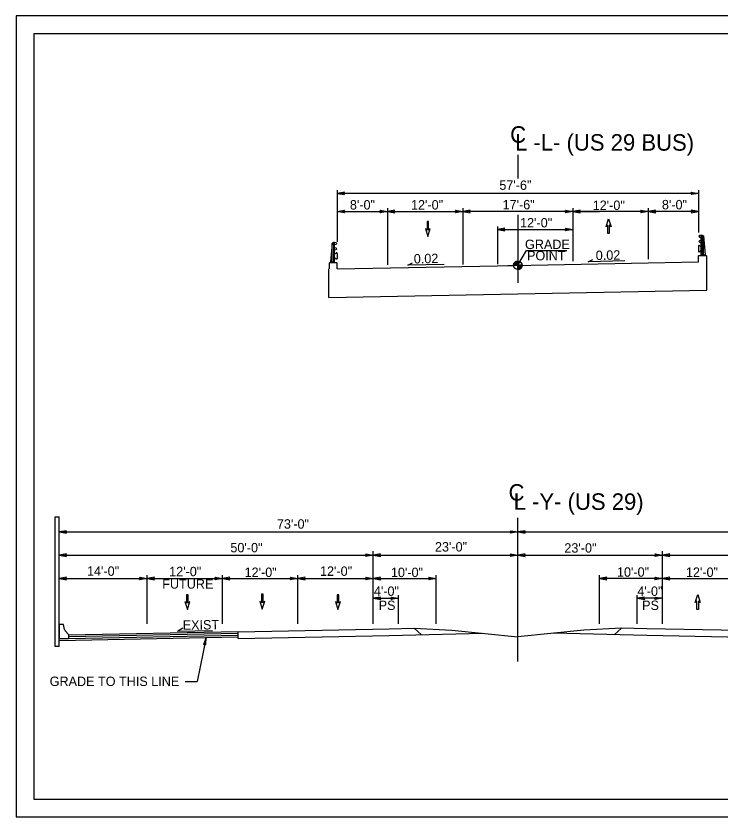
# Model space of a CAD drawing. Extents: x 1901582 to 1902252, y 193723 to 194156.
# Drawn here: x 1901677.8 to 1901790, y 193784.8 to 193912.3 of the extents above; entities that cross this region are included whole.
import ezdxf

# ---------------------------------------------------------------- set-up
doc = ezdxf.new("R2010")
doc.units = 0
for name, color, linetype in [('Old_Level_1', 7, 'Continuous'), ('Old_Level_11', 7, 'Continuous'), ('Old_Level_2', 7, 'Continuous'), ('Prop Dimension', 7, 'Continuous'), ('Prop Dimension Text', 7, 'Continuous'), ('Prop Roadway Bridge', 7, 'Continuous'), ('Scratch_Level_0', 7, 'Continuous'), ('Typical Bridge Rail CELL', 7, 'Continuous'), ('Typical Grade Point Symbol CELL', 7, 'Continuous'), ('Typical Pavement Slope CELL', 7, 'Continuous'), ('Typical Pavement Slope Information CELL', 7, 'Continuous'), ('Typical Terminator CELL', 7, 'Continuous'), ('Typical Text Centerline CELL', 7, 'Continuous'), ('Typical Text Grade Point CELL', 7, 'Continuous')]:
    doc.layers.add(name, color=color, linetype=linetype)

msp = doc.modelspace()

# ---------------------------------------------------------------- linework, layer by layer
at = {"layer": 'Old_Level_1'}
for p, q in [((1901728.9, 193884.55), (1901728.9, 193876.32)), ((1901786.4, 193884.55), (1901786.4, 193877.8)), ((1901736.9, 193881.68), (1901736.9, 193872.69)), ((1901748.9, 193881.68), (1901748.9, 193872.73)), ((1901766.4, 193881.68), (1901766.4, 193873.28)), ((1901778.4, 193881.68), (1901778.4, 193873.6)), ((1901754.4, 193878.8), (1901754.4, 193872.8)), ((1901786.41, 193875.65), (1901786.41, 193874.85)), ((1901786.82, 193875.5), (1901786.54, 193875.73)), ((1901728.48, 193874.35), (1901728.75, 193874.58)), ((1901728.89, 193874.5), (1901728.89, 193873.7)), ((1901786.4, 193874.09), (1901786.47, 193874.17)), ((1901786.4, 193873.17), (1901786.4, 193874.09)), ((1901786.47, 193874.17), (1901787.63, 193874.17)), ((1901786.82, 193875), (1901786.54, 193874.77)), ((1901786.66, 193874.16), (1901786.74, 193874.16)), ((1901787.35, 193874.16), (1901787.41, 193874.16)), ((1901787.69, 193874.1), (1901787.63, 193874.17)), ((1901787.69, 193874.1), (1901787.69, 193873.17)), ((1901727.61, 193872.95), (1901727.67, 193873.02)), ((1901727.61, 193872.95), (1901727.61, 193872.02)), ((1901728.83, 193873.02), (1901727.67, 193873.02)), ((1901727.95, 193873.01), (1901727.89, 193873.01)), ((1901728.48, 193873.85), (1901728.75, 193873.62)), ((1901728.64, 193873.01), (1901728.56, 193873.01)), ((1901728.9, 193872.94), (1901728.83, 193873.02)), ((1901728.9, 193872.02), (1901728.9, 193872.94)), ((1901754.4, 193872.53), (1901786.4, 193873.17)), ((1901787.69, 193873.17), (1901787.73, 193873.17)), ((1901787.73, 193868.67), (1901787.73, 193873.17)), ((1901727.57, 193867.47), (1901727.57, 193872.02)), ((1901728.9, 193872.02), (1901754.4, 193872.53)), ((1901727.57, 193867.47), (1901787.73, 193868.67)), ((1901713.15, 193814.26), (1901686.15, 193813.72)), ((1901713.15, 193814.26), (1901737.15, 193814.74)), ((1901713.15, 193813.18), (1901713.15, 193814.26)), ((1901737.15, 193814.74), (1901741.15, 193814.84)), ((1901737.15, 193813.67), (1901752, 193814.04)), ((1901741.15, 193814.84), (1901747.15, 193814.53)), ((1901741.15, 193814.84), (1901742.31, 193813.8)), ((1901747.15, 193814.53), (1901757.65, 193813.48)), ((1901768.15, 193814.53), (1901757.65, 193813.48)), ((1901778.15, 193813.67), (1901763.3, 193814.04)), ((1901774.15, 193814.84), (1901768.15, 193814.53)), ((1901774.15, 193814.84), (1901772.99, 193813.8)), ((1901778.15, 193814.74), (1901774.15, 193814.84)), ((1901814.15, 193814.02), (1901778.15, 193814.74)), ((1901708.06, 193813.33), (1901706.61, 193806.37)), ((1901704.7, 193806.37), (1901706.61, 193806.37))]:
    msp.add_line(p, q, dxfattribs=at)
msp.add_lwpolyline([(1901839.99, 193787.6), (1901839.99, 193909.47), (1901680.62, 193909.47), (1901680.62, 193787.6)], close=True, dxfattribs=at)
for points in [[(1901786.83, 193877.38), (1901786.98, 193877.38), (1901787.18, 193877.3), (1901787.2, 193877.3), (1901787.45, 193874.27), (1901787.45, 193874.24), (1901786.83, 193874.24), (1901786.83, 193877.38), (1901786.98, 193877.38), (1901786.98, 193874.24), (1901787.18, 193874.24), (1901787.18, 193877.3)], [(1901728.47, 193876.23), (1901728.32, 193876.23), (1901728.11, 193876.15), (1901728.09, 193876.15), (1901727.85, 193873.12), (1901727.85, 193873.09), (1901728.47, 193873.09), (1901728.47, 193876.23), (1901728.32, 193876.23), (1901728.32, 193873.09), (1901728.11, 193873.09), (1901728.11, 193876.15)], [(1901713.15, 193813.18), (1901737.15, 193813.66)], [(1901814.14, 193812.94), (1901778.15, 193813.66)]]:
    msp.add_lwpolyline(points, dxfattribs=at)
for centre, start, end in [((1901786.49, 193875.66), 50.5568, 186.0672), ((1901728.81, 193874.51), 353.9328, 129.4432), ((1901786.49, 193874.84), 173.9328, 309.4432), ((1901728.81, 193873.69), 230.5568, 6.0672)]:
    msp.add_arc(centre, 0.0824, start, end, dxfattribs=at)
for centre, major_axis, start_param, end_param in [((1901786.83, 193877.22), (-0.392, 0), 4.712389, 6.283185), ((1901786.83, 193877.22), (-0.392, 0), 0, 1.570796), ((1901786.83, 193876.39), (-0.392, 0), 4.712389, 6.283185), ((1901728.47, 193876.07), (0.392, 0), 0, 1.570796), ((1901728.47, 193876.07), (0.392, 0), 4.712389, 6.283185), ((1901728.47, 193875.24), (0.392, 0), 0, 1.570796), ((1901728.47, 193875.24), (0.392, 0), 4.712389, 6.283185), ((1901786.83, 193876.39), (-0.392, 0), 0, 1.570796)]:
    msp.add_ellipse(centre, major_axis=major_axis, ratio=0.42124, start_param=start_param, end_param=end_param, dxfattribs=at)
at = {"layer": 'Old_Level_11'}
for p, q in [((1901757.65, 193890.19), (1901757.65, 193886.4)), ((1901757.65, 193880.63), (1901757.65, 193869.8)), ((1901757.65, 193809.51), (1901757.65, 193832.38))]:
    msp.add_line(p, q, dxfattribs=at)
at = {"layer": 'Prop Dimension'}
for p, q in [((1901684.65, 193830.16), (1901757.65, 193830.16)), ((1901757.65, 193830.16), (1901836.65, 193830.16)), ((1901734.65, 193815.55), (1901734.65, 193827.11)), ((1901780.65, 193815.55), (1901780.65, 193827.11)), ((1901684.65, 193826.46), (1901734.65, 193826.46)), ((1901734.65, 193826.46), (1901757.65, 193826.46)), ((1901757.65, 193826.46), (1901780.65, 193826.46)), ((1901780.65, 193826.46), (1901836.65, 193826.46)), ((1901698.65, 193815.55), (1901698.65, 193823.26)), ((1901710.65, 193815.55), (1901710.65, 193823.26)), ((1901722.65, 193815.55), (1901722.65, 193823.26)), ((1901744.65, 193815.55), (1901744.65, 193823.26)), ((1901770.65, 193815.55), (1901770.65, 193823.26)), ((1901684.65, 193822.76), (1901698.65, 193822.76)), ((1901698.65, 193822.76), (1901710.65, 193822.76)), ((1901710.65, 193822.76), (1901722.65, 193822.76)), ((1901722.65, 193822.76), (1901734.65, 193822.76)), ((1901734.65, 193822.76), (1901744.65, 193822.76)), ((1901780.65, 193822.76), (1901770.65, 193822.76)), ((1901780.65, 193822.76), (1901792.65, 193822.76)), ((1901734.65, 193819.6), (1901738.65, 193819.6)), ((1901738.65, 193815.55), (1901738.65, 193820.07)), ((1901776.65, 193815.55), (1901776.65, 193820.07)), ((1901780.65, 193819.6), (1901776.65, 193819.6)), ((1901713.15, 193813.42), (1901684.65, 193812.85)), ((1901713.15, 193814.01), (1901686.15, 193813.47)), ((1901713.16, 193813.68), (1901686.15, 193813.13))]:
    msp.add_line(p, q, dxfattribs=at)
for points in [[(1901743.72, 193878.47), (1901743.45, 193878.22), (1901743.45, 193879.55), (1901743.2, 193879.55), (1901743.2, 193878.22), (1901742.93, 193878.47), (1901743.33, 193877.2)], [(1901743.72, 193878.47), (1901743.45, 193878.22), (1901743.45, 193879.55), (1901743.2, 193879.55), (1901743.2, 193878.22), (1901742.93, 193878.47), (1901743.33, 193877.2)], [(1901772.47, 193878.74), (1901772.2, 193878.99), (1901772.2, 193877.66), (1901771.95, 193877.66), (1901771.95, 193878.99), (1901771.68, 193878.74), (1901772.08, 193880.01)], [(1901772.47, 193878.74), (1901772.2, 193878.99), (1901772.2, 193877.66), (1901771.95, 193877.66), (1901771.95, 193878.99), (1901771.68, 193878.74), (1901772.08, 193880.01)], [(1901705.47, 193819.09), (1901705.2, 193818.84), (1901705.2, 193820.17), (1901704.95, 193820.17), (1901704.95, 193818.84), (1901704.68, 193819.09), (1901705.07, 193817.81)], [(1901717.39, 193819.15), (1901717.12, 193818.9), (1901717.12, 193820.24), (1901716.87, 193820.24), (1901716.87, 193818.9), (1901716.6, 193819.15), (1901716.99, 193817.88)], [(1901717.39, 193819.15), (1901717.12, 193818.9), (1901717.12, 193820.24), (1901716.87, 193820.24), (1901716.87, 193818.9), (1901716.6, 193819.15), (1901716.99, 193817.88)], [(1901729.41, 193819.07), (1901729.14, 193818.82), (1901729.14, 193820.16), (1901728.89, 193820.16), (1901728.89, 193818.82), (1901728.62, 193819.07), (1901729.02, 193817.8)], [(1901729.41, 193819.07), (1901729.14, 193818.82), (1901729.14, 193820.16), (1901728.89, 193820.16), (1901728.89, 193818.82), (1901728.62, 193819.07), (1901729.02, 193817.8)], [(1901786.66, 193818.91), (1901786.39, 193819.16), (1901786.39, 193817.83), (1901786.14, 193817.83), (1901786.14, 193819.16), (1901785.87, 193818.91), (1901786.26, 193820.18)], [(1901786.66, 193818.91), (1901786.39, 193819.16), (1901786.39, 193817.83), (1901786.14, 193817.83), (1901786.14, 193819.16), (1901785.87, 193818.91), (1901786.26, 193820.18)]]:
    msp.add_lwpolyline(points, close=True, dxfattribs=at)
at = {"layer": 'Prop Dimension Text'}
for p, q in [((1901786.4, 193884.05), (1901728.9, 193884.05)), ((1901728.9, 193881.18), (1901736.9, 193881.18)), ((1901736.9, 193881.18), (1901748.9, 193881.18)), ((1901737.65, 193881.18), (1901748.65, 193881.18)), ((1901766.4, 193881.18), (1901748.9, 193881.18)), ((1901778.4, 193881.18), (1901766.4, 193881.18)), ((1901777.65, 193881.18), (1901766.65, 193881.18)), ((1901766.65, 193881.18), (1901770.65, 193881.18)), ((1901786.4, 193881.18), (1901778.4, 193881.18)), ((1901754.4, 193878.3), (1901766.4, 193878.3))]:
    msp.add_line(p, q, dxfattribs=at)
at = {"layer": 'Prop Roadway Bridge'}
for p, q in [((1901727.61, 193872.02), (1901727.57, 193872.02)), ((1901684.01, 193811.94), (1901684.01, 193832.57)), ((1901684.01, 193832.57), (1901684.65, 193832.57)), ((1901684.65, 193811.94), (1901684.65, 193832.57)), ((1901684.65, 193811.94), (1901684.01, 193811.94))]:
    msp.add_line(p, q, dxfattribs=at)
at = {"layer": 'Scratch_Level_0'}
msp.add_lwpolyline([(1901842.8, 193784.79), (1901842.8, 193912.29), (1901677.8, 193912.29), (1901677.8, 193784.79)], close=True, dxfattribs=at)
at = {"layer": 'Typical Bridge Rail CELL'}
for p, q in [((1901684.68, 193815.41), (1901684.65, 193815.38)), ((1901684.65, 193815.38), (1901684.65, 193813.18)), ((1901685.35, 193815.41), (1901684.68, 193815.41)), ((1901685.52, 193814.64), (1901685.35, 193815.41)), ((1901686.15, 193813.84), (1901685.64, 193814.4)), ((1901684.65, 193813.18), (1901686.15, 193813.18)), ((1901686.15, 193813.84), (1901686.15, 193813.18))]:
    msp.add_line(p, q, dxfattribs=at)
msp.add_arc((1901686.01, 193814.74), 0.5, 191.9958, 222.1301, dxfattribs=at)
at = {"layer": 'Typical Grade Point Symbol CELL'}
for p, q in [((1901757.65, 193872.6), (1901757.65, 193873.27)), ((1901756.98, 193872.6), (1901757.65, 193872.6)), ((1901757.65, 193871.93), (1901757.65, 193872.6)), ((1901758.32, 193872.6), (1901757.65, 193872.6)), ((1901757.65, 193872.6), (1901757.65, 193871.93))]:
    msp.add_line(p, q, dxfattribs=at)
for points in [[(1901756.99, 193872.69), (1901756.99, 193872.6)], [(1901757, 193872.76), (1901757, 193872.6)], [(1901757.01, 193872.81), (1901757.01, 193872.6)], [(1901757.03, 193872.85), (1901757.03, 193872.6)], [(1901757.04, 193872.88), (1901757.04, 193872.6)], [(1901757.05, 193872.91), (1901757.05, 193872.6)], [(1901757.07, 193872.93), (1901757.07, 193872.6)], [(1901757.08, 193872.95), (1901757.08, 193872.6)], [(1901757.09, 193872.97), (1901757.09, 193872.6)], [(1901757.11, 193872.99), (1901757.11, 193872.6)], [(1901757.12, 193873.01), (1901757.12, 193872.6)], [(1901757.13, 193873.03), (1901757.13, 193872.6)], [(1901757.15, 193873.04), (1901757.15, 193872.6)], [(1901757.16, 193873.06), (1901757.16, 193872.6)], [(1901757.17, 193873.07), (1901757.17, 193872.6)], [(1901757.19, 193873.08), (1901757.19, 193872.6)], [(1901757.2, 193873.1), (1901757.2, 193872.6)], [(1901757.21, 193873.11), (1901757.21, 193872.6)], [(1901757.23, 193873.12), (1901757.23, 193872.6)], [(1901757.24, 193873.13), (1901757.24, 193872.6)], [(1901757.25, 193873.14), (1901757.25, 193872.6)], [(1901757.27, 193873.15), (1901757.27, 193872.6)], [(1901757.28, 193873.16), (1901757.28, 193872.6)], [(1901757.29, 193873.17), (1901757.29, 193872.6)], [(1901757.31, 193873.18), (1901757.31, 193872.6)], [(1901757.32, 193873.18), (1901757.32, 193872.6)], [(1901757.33, 193873.19), (1901757.33, 193872.6)], [(1901757.35, 193873.2), (1901757.35, 193872.6)], [(1901757.36, 193873.2), (1901757.36, 193872.6)], [(1901757.37, 193873.21), (1901757.37, 193872.6)], [(1901757.39, 193873.22), (1901757.39, 193872.6)], [(1901757.4, 193873.22), (1901757.4, 193872.6)], [(1901757.41, 193873.23), (1901757.41, 193872.6)], [(1901757.43, 193873.23), (1901757.43, 193872.6)], [(1901757.44, 193873.24), (1901757.44, 193872.6)], [(1901757.46, 193873.24), (1901757.46, 193872.6)], [(1901757.47, 193873.24), (1901757.47, 193872.6)], [(1901757.48, 193873.25), (1901757.48, 193872.6)], [(1901757.5, 193873.25), (1901757.5, 193872.6)], [(1901757.51, 193873.26), (1901757.51, 193872.6)], [(1901757.52, 193873.26), (1901757.52, 193872.6)], [(1901757.54, 193873.26), (1901757.54, 193872.6)], [(1901757.55, 193873.26), (1901757.55, 193872.6)], [(1901757.56, 193873.26), (1901757.56, 193872.6)], [(1901757.58, 193873.27), (1901757.58, 193872.6)], [(1901757.59, 193873.27), (1901757.59, 193872.6)], [(1901757.6, 193873.27), (1901757.6, 193872.6)], [(1901757.62, 193873.27), (1901757.62, 193872.6)], [(1901757.63, 193873.27), (1901757.63, 193872.6)], [(1901757.64, 193873.27), (1901757.64, 193873.27), (1901757.64, 193872.6)], [(1901757.66, 193872.6), (1901757.66, 193871.93), (1901757.66, 193871.93)], [(1901757.67, 193872.6), (1901757.67, 193871.93)], [(1901757.69, 193872.6), (1901757.69, 193871.93)], [(1901757.7, 193872.6), (1901757.7, 193871.93)], [(1901757.71, 193872.6), (1901757.71, 193871.93)], [(1901757.73, 193872.6), (1901757.73, 193871.93)], [(1901757.74, 193872.6), (1901757.74, 193871.93)], [(1901757.75, 193872.6), (1901757.75, 193871.94)], [(1901757.77, 193872.6), (1901757.77, 193871.94)], [(1901757.78, 193872.6), (1901757.78, 193871.94)], [(1901757.79, 193872.6), (1901757.79, 193871.94)], [(1901757.81, 193872.6), (1901757.81, 193871.95)], [(1901757.82, 193872.6), (1901757.82, 193871.95)], [(1901757.83, 193872.6), (1901757.83, 193871.95)], [(1901757.85, 193872.6), (1901757.85, 193871.96)], [(1901757.86, 193872.6), (1901757.86, 193871.96)], [(1901757.87, 193872.6), (1901757.87, 193871.97)], [(1901757.89, 193872.6), (1901757.89, 193871.97)], [(1901757.9, 193872.6), (1901757.9, 193871.98)], [(1901757.91, 193872.6), (1901757.91, 193871.98)], [(1901757.93, 193872.6), (1901757.93, 193871.99)], [(1901757.94, 193872.6), (1901757.94, 193871.99)], [(1901757.95, 193872.6), (1901757.95, 193872)], [(1901757.97, 193872.6), (1901757.97, 193872.01)], [(1901757.98, 193872.6), (1901757.98, 193872.02)], [(1901758, 193872.6), (1901758, 193872.02)], [(1901758.01, 193872.6), (1901758.01, 193872.03)], [(1901758.02, 193872.6), (1901758.02, 193872.04)], [(1901758.04, 193872.6), (1901758.04, 193872.05)], [(1901758.05, 193872.6), (1901758.05, 193872.06)], [(1901758.06, 193872.6), (1901758.06, 193872.07)], [(1901758.08, 193872.6), (1901758.08, 193872.08)], [(1901758.09, 193872.6), (1901758.09, 193872.09)], [(1901758.1, 193872.6), (1901758.1, 193872.1)], [(1901758.12, 193872.6), (1901758.12, 193872.12)], [(1901758.13, 193872.6), (1901758.13, 193872.13)], [(1901758.14, 193872.6), (1901758.14, 193872.14)], [(1901758.16, 193872.6), (1901758.16, 193872.16)], [(1901758.17, 193872.6), (1901758.17, 193872.17)], [(1901758.18, 193872.6), (1901758.18, 193872.19)], [(1901758.2, 193872.6), (1901758.2, 193872.21)], [(1901758.21, 193872.6), (1901758.21, 193872.23)], [(1901758.22, 193872.6), (1901758.22, 193872.25)], [(1901758.24, 193872.6), (1901758.24, 193872.27)], [(1901758.25, 193872.6), (1901758.25, 193872.3)], [(1901758.26, 193872.6), (1901758.26, 193872.33)], [(1901758.28, 193872.6), (1901758.28, 193872.36)], [(1901758.29, 193872.6), (1901758.29, 193872.4)], [(1901758.3, 193872.6), (1901758.3, 193872.45)], [(1901758.32, 193872.6), (1901758.32, 193872.53)]]:
    msp.add_lwpolyline(points, dxfattribs=at)
msp.add_circle((1901757.65, 193872.6), 0.671, dxfattribs=at)
for start, end in [(90.0095, 180.0095), (270.0095, 0.0095)]:
    msp.add_arc((1901757.65, 193872.6), 0.671, start, end, dxfattribs=at)
at = {"layer": 'Typical Pavement Slope CELL'}
msp.add_line((1901754.4, 193872.53), (1901757.65, 193872.6), dxfattribs=at)
at = {"layer": 'Typical Pavement Slope Information CELL'}
for p, q in [((1901740.13, 193872.61), (1901740.88, 193872.99)), ((1901745.95, 193872.75), (1901740.13, 193872.61)), ((1901768.83, 193873.17), (1901769.57, 193873.54)), ((1901774.65, 193873.31), (1901768.83, 193873.17)), ((1901703.48, 193814.36), (1901704.32, 193814.87)), ((1901703.48, 193814.36), (1901709.04, 193814.47))]:
    msp.add_line(p, q, dxfattribs=at)
at = {"layer": 'Typical Terminator CELL'}
for points in [[(1901730.07, 193884.26), (1901728.9, 193884.05), (1901730.08, 193883.85), (1901729.93, 193884.05)], [(1901785.23, 193884.26), (1901786.4, 193884.05), (1901785.22, 193883.85), (1901785.37, 193884.05)], [(1901730.07, 193880.98), (1901728.9, 193881.18), (1901730.08, 193881.39), (1901729.93, 193881.18)], [(1901735.73, 193881.38), (1901736.9, 193881.18), (1901735.72, 193880.97), (1901735.87, 193881.18)], [(1901738.07, 193881.38), (1901736.9, 193881.18), (1901738.08, 193880.97), (1901737.93, 193881.18)], [(1901747.73, 193881.38), (1901748.9, 193881.18), (1901747.72, 193880.97), (1901747.87, 193881.18)], [(1901750.07, 193881.38), (1901748.9, 193881.18), (1901750.08, 193880.97), (1901749.93, 193881.18)], [(1901765.23, 193881.38), (1901766.4, 193881.18), (1901765.22, 193880.97), (1901765.37, 193881.18)], [(1901767.57, 193881.38), (1901766.4, 193881.18), (1901767.58, 193880.97), (1901767.43, 193881.18)], [(1901777.23, 193881.38), (1901778.4, 193881.18), (1901777.22, 193880.97), (1901777.37, 193881.18)], [(1901779.57, 193881.38), (1901778.4, 193881.18), (1901779.58, 193880.97), (1901779.43, 193881.18)], [(1901785.23, 193880.98), (1901786.4, 193881.18), (1901785.22, 193881.39), (1901785.37, 193881.18)], [(1901755.57, 193878.51), (1901754.4, 193878.3), (1901755.58, 193878.1), (1901755.43, 193878.3)], [(1901765.23, 193878.51), (1901766.4, 193878.3), (1901765.22, 193878.1), (1901765.37, 193878.3)], [(1901685.82, 193830.36), (1901684.65, 193830.16), (1901685.83, 193829.95), (1901685.68, 193830.16)], [(1901756.48, 193830.36), (1901757.65, 193830.16), (1901756.47, 193829.95), (1901756.62, 193830.16)], [(1901758.82, 193830.36), (1901757.65, 193830.16), (1901758.83, 193829.95), (1901758.68, 193830.16)], [(1901685.82, 193826.66), (1901684.65, 193826.46), (1901685.83, 193826.25), (1901685.68, 193826.46)], [(1901733.48, 193826.66), (1901734.65, 193826.46), (1901733.47, 193826.25), (1901733.62, 193826.46)], [(1901735.82, 193826.66), (1901734.65, 193826.46), (1901735.83, 193826.25), (1901735.68, 193826.46)], [(1901756.48, 193826.66), (1901757.65, 193826.46), (1901756.47, 193826.25), (1901756.62, 193826.46)], [(1901758.82, 193826.66), (1901757.65, 193826.46), (1901758.83, 193826.25), (1901758.68, 193826.46)], [(1901779.48, 193826.66), (1901780.65, 193826.46), (1901779.47, 193826.25), (1901779.62, 193826.46)], [(1901781.82, 193826.66), (1901780.65, 193826.46), (1901781.83, 193826.25), (1901781.68, 193826.46)], [(1901685.82, 193822.96), (1901684.65, 193822.76), (1901685.83, 193822.55), (1901685.68, 193822.76)], [(1901697.48, 193822.96), (1901698.65, 193822.76), (1901697.47, 193822.55), (1901697.62, 193822.76)], [(1901699.82, 193822.96), (1901698.65, 193822.76), (1901699.83, 193822.55), (1901699.68, 193822.76)], [(1901709.48, 193822.96), (1901710.65, 193822.76), (1901709.47, 193822.55), (1901709.62, 193822.76)], [(1901711.82, 193822.96), (1901710.65, 193822.76), (1901711.83, 193822.55), (1901711.68, 193822.76)], [(1901721.48, 193822.96), (1901722.65, 193822.76), (1901721.47, 193822.55), (1901721.62, 193822.76)], [(1901723.82, 193822.96), (1901722.65, 193822.76), (1901723.83, 193822.55), (1901723.68, 193822.76)], [(1901733.48, 193822.96), (1901734.65, 193822.76), (1901733.47, 193822.55), (1901733.62, 193822.76)], [(1901735.82, 193822.96), (1901734.65, 193822.76), (1901735.83, 193822.55), (1901735.68, 193822.76)], [(1901743.5, 193822.95), (1901744.67, 193822.75), (1901743.49, 193822.54), (1901743.64, 193822.75)], [(1901771.8, 193822.95), (1901770.63, 193822.75), (1901771.81, 193822.54), (1901771.66, 193822.75)], [(1901779.48, 193822.96), (1901780.65, 193822.76), (1901779.47, 193822.55), (1901779.62, 193822.76)], [(1901781.82, 193822.96), (1901780.65, 193822.76), (1901781.83, 193822.55), (1901781.68, 193822.76)], [(1901735.82, 193819.8), (1901734.65, 193819.6), (1901735.83, 193819.39), (1901735.68, 193819.6)], [(1901737.48, 193819.8), (1901738.65, 193819.6), (1901737.47, 193819.39), (1901737.62, 193819.6)], [(1901777.82, 193819.8), (1901776.65, 193819.6), (1901777.83, 193819.39), (1901777.68, 193819.6)], [(1901779.48, 193819.8), (1901780.65, 193819.6), (1901779.47, 193819.39), (1901779.62, 193819.6)], [(1901708.02, 193812.17), (1901708.06, 193813.33), (1901707.63, 193812.25), (1901707.86, 193812.35)]]:
    msp.add_lwpolyline(points, close=True, dxfattribs=at)
at = {"layer": 'Typical Text Grade Point CELL'}
for p, q in [((1901757.65, 193872.6), (1901759.05, 193874.96)), ((1901759.05, 193874.96), (1901765.46, 193874.96))]:
    msp.add_line(p, q, dxfattribs=at)

# ---------------------------------------------------------------- texts
at = {"layer": 'Old_Level_1'}
for s, p in [('73\'-0"', (1901719.31, 193830.68)), ('50\'-0"', (1901711.91, 193826.91)), ('23\'-0"', (1901744.46, 193827.04)), ('23\'-0"', (1901765.05, 193826.86)), ('14\'-0"', (1901689.1, 193823.18)), ('12\'-0"', (1901702.17, 193823.11)), ('12\'-0"', (1901714.17, 193822.99)), ('12\'-0"', (1901726.17, 193823.17)), ('10\'-0"', (1901737.45, 193822.97)), ('10\'-0"', (1901773.42, 193823.03)), ('12\'-0"', (1901784.39, 193823)), ('4\'-0"', (1901734.74, 193819.98)), ('4\'-0"', (1901776.66, 193819.98)), ('GRADE TO THIS LINE', (1901683.16, 193805.63))]:
    msp.add_text(s, height=1.5, dxfattribs=at).set_placement(p)
at = {"layer": 'Old_Level_2'}
for s, rotation, p in [('0.02', 1.1916, (1901741.11, 193872.89)), ('0.02', 1.1916, (1901770.06, 193873.43)), ('EXIST', 0.7985, (1901704.33, 193814.58))]:
    msp.add_text(s, height=1.5, rotation=rotation, dxfattribs=at).set_placement(p)
at = {"layer": 'Prop Dimension Text'}
for s, p in [('57\'-6"', (1901754.7, 193884.61)), ('8\'-0"', (1901730.93, 193881.48)), ('12\'-0"', (1901740.65, 193881.48)), ('17\'-6"', (1901755.22, 193881.51)), ('12\'-0"', (1901769.56, 193881.41)), ('8\'-0"', (1901780.57, 193881.51)), ('12\'-0"', (1901758, 193878.63)), ('FUTURE', (1901701.07, 193821.13)), ('PS', (1901735.5, 193817.73)), ('PS', (1901777.42, 193817.73))]:
    msp.add_text(s, height=1.5, dxfattribs=at).set_placement(p)
at = {"layer": 'Typical Text Centerline CELL'}
for height, p in [(2.63, (1901756.42, 193892.11)), (2.62, (1901756.17, 193835.14))]:
    msp.add_text('C', height=height, dxfattribs=at).set_placement(p)
for s, p in [('L -L- (US 29 BUS)', (1901757.2, 193890.87)), ('L -Y- (US 29)', (1901756.98, 193833.69))]:
    msp.add_text(s, height=2.6257, rotation=359.9469, dxfattribs=at).set_placement(p)
at = {"layer": 'Typical Text Grade Point CELL'}
for s, p in [('GRADE', (1901758.79, 193875.19)), ('POINT', (1901759.11, 193873.39))]:
    msp.add_text(s, height=1.5, dxfattribs=at).set_placement(p)

doc.saveas('drawing.dxf')
